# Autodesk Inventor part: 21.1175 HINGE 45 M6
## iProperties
Created: 2007-01
Part Number: 21.1175 HINGE 45 M6
Document SubType Name: Modeling
Designer: Andy Moles
Material: Steel
Density: 7.85 g/cm^3
Author: Andy Moles
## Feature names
1. Extrusion1
2. Chamfer1
